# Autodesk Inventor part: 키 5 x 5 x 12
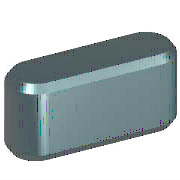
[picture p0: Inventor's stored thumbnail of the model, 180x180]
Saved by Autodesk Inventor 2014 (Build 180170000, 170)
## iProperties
IsCustomPart: 1
Created: 2012-02
Part Number: 키 5 x 5 x 12
Material: 강철, 연강
Description: 키 및 해당 키홈
Document SubType Name: Modeling
Standard: KS B 1311
Designer: mduedu
Standards Organization: KS
Language: ko-KR
Size Designation: 5 x 5 x 12
Categories: <MemberInstance><Categories><Category DisplayName="샤프트 부품" InternalName="7f7aeb1f-a693-4053-b835-cee3144e0d98" Mnemonic="SHFT"><Category DisplayName="키" Interna
Density: 7.86 g/cm^3
Mass: 2.11085 g
Surface Area: 2.43471 cm^2
Volume: 0.268556 cm^3
Appearance: 노란색
Author: mduedu
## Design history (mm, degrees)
workplane "Work Plane1"
workplane "Work Plane2"
sketch "스케치1"
  geometry: L1 (2.5, 2.5)-(9.5, 2.5); L2 (9.5, -2.5)-(2.5, -2.5); L3 (0, 9.4)-(0, -7.4) reference; L4 (-5, 0)-(30, 0) reference; L5 (12, 0)-(12, 7); A1 r 2.5 centre (2.5, 0) between (2.5, 2.5) and (2.5, -2.5); A2 r 2.5 centre (9.5, 0) between (9.5, -2.5) and (9.5, 2.5)
  constraints: 6 end point, 5 point on circle, 4 tangent, 3 point on line, 2 centre point, 1 horizontal, 1 parallel, 1 perpendicular
  dimensions: "d0" = 2.5 radius of A1 (= 0.5 x PB); "d13" = 2.5 radius of A2 (= 0.5 x PB); "d14" = 12 distance between parallel lines of L5 L3 (= NLG)
extrude "본체1" new body sketch "스케치1" taper "d3" = 0 deg; stored distance "d4" = 10
workplane "Work Plane3"
body "Solid1"
chamfer "모따기1" distance "d8" = 0.4 (= PHH); stored, may be unused: second distance "d9" = 0.4 (= PHH), angle "d15" = 45 deg
other parameters: "d1" = -3 (= -PNT), "d2" = 2 (= PH - PNT), "NLG" = 12 [user parameter; used in 3 equation terms], "PB" = 5 [user parameter; used in 2 equation terms], "PNT" = 3 [user parameter; used in 2 equation terms], "PH" = 5 [user parameter; used in 1 equation term], "PHH" = 0.4 [user parameter; used in 2 equation terms], "d10" = 0, "d16" = 0, "d17" = 0, "d18" = 0, "WDMIN" = 12 [user parameter], "PLB2" = 12 (= NLG) [user parameter], "WDMAX" = 17 [user parameter], "PLB1" = 12 (= NLG) [user parameter], "RR" = 0.16 [user parameter], "PUEB" = 2.3 [user parameter]
